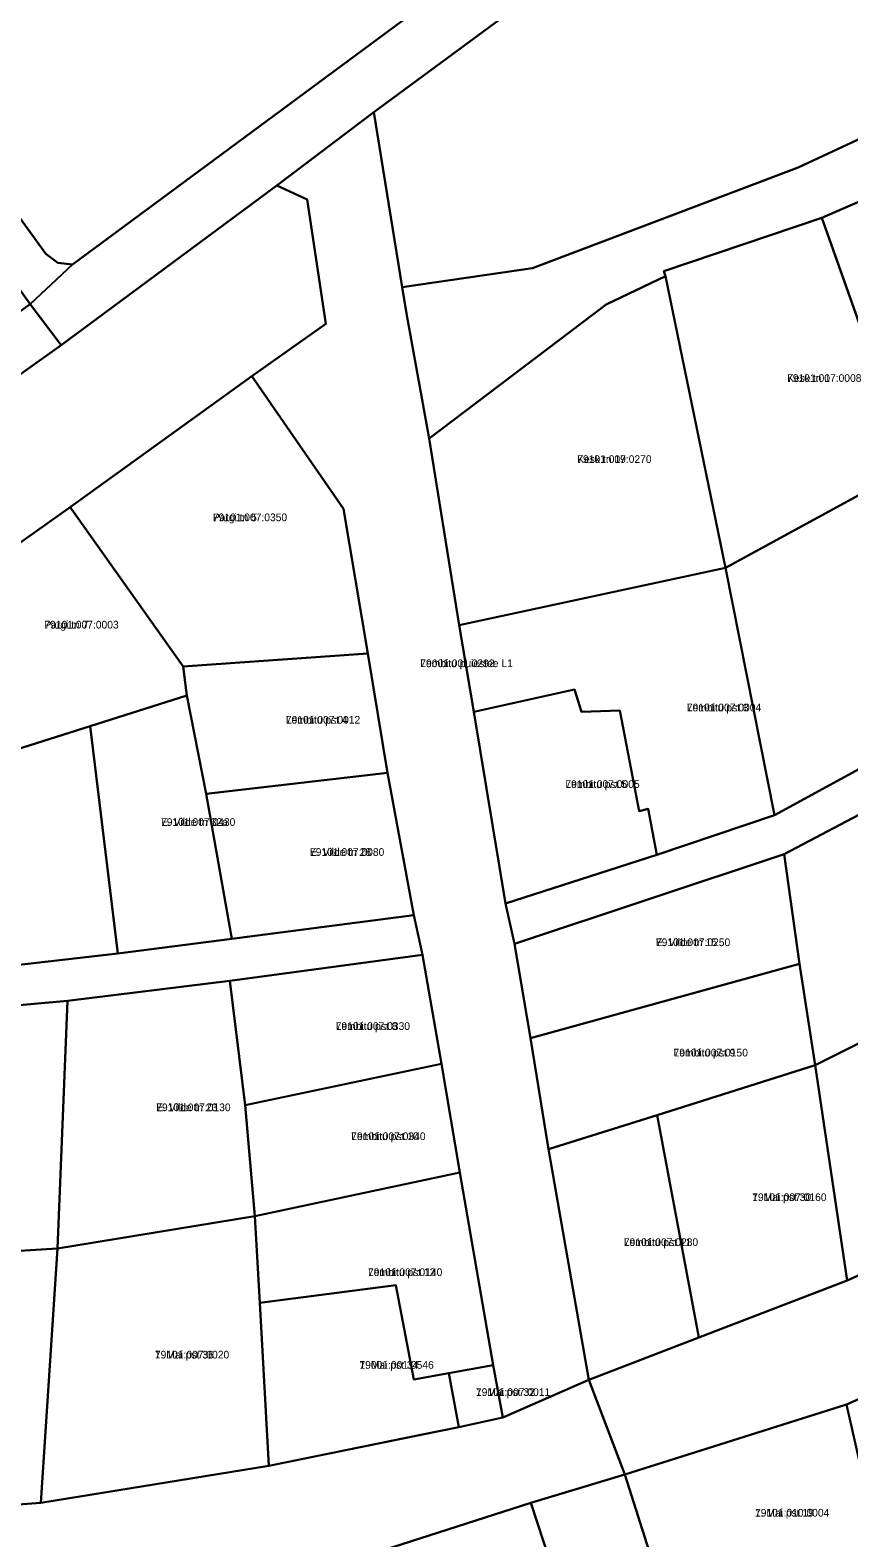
# Model space of a CAD drawing. Extents: x 587616 to 632239, y 6547421 to 6574977.
# Drawn here: x 611446.6 to 611606.3, y 6570695.1 to 6570989.5 of the extents above; entities that cross this region are included whole.
import ezdxf

# ---------------------------------------------------------------- set-up
doc = ezdxf.new("R2010")
doc.units = 0
for name, color, linetype in [('L_AADRESS', 7, 'Continuous'), ('PIIR', 7, 'Continuous'), ('TUNNUS', 7, 'Continuous')]:
    doc.layers.add(name, color=color, linetype=linetype)

msp = doc.modelspace()

# ---------------------------------------------------------------- linework, layer by layer
at = {"layer": 'PIIR'}
for points in [[(611446.63, 6570935.99), (611454.85, 6570943.73), (611564.19, 6571024.58), (611574.16, 6571034.86), (611617.76, 6571067.56), (611639.31, 6571081.15), (611661.96, 6571097.69), (611699.21, 6571124.46), (611732.93, 6571149.12), (611742.94, 6571156.35), (611778.1, 6571182.02), (611797.02, 6571195.84), (611810.31, 6571205.47), (611838.63, 6571226.7), (611846.22, 6571216.07), (611796.12, 6571181.57), (611778.84, 6571168.84), (611746.37, 6571145.45), (611736.9, 6571139.34), (611649.26, 6571075.47), (611632.53, 6571061.07), (611513.67, 6570973.46), (611494.74, 6570959.13), (611452.66, 6570927.93)], [(611556.99, 6571124.68), (611590.3, 6571148.55), (611614.86, 6571115.38), (611639.31, 6571081.15), (611617.76, 6571067.56), (611574.16, 6571034.86), (611564.19, 6571024.58), (611454.85, 6570943.73), (611452.04, 6570944.05), (611449.7, 6570945.77), (611402.13, 6571011.47), (611505.14, 6571086.78)], [(611513.67, 6570973.46), (611632.53, 6571061.07), (611674.1, 6571008.09), (611673.76, 6570998.68), (611596.46, 6570962.66), (611544.61, 6570943), (611519.18, 6570939.27)], [(611395.22, 6571006.93), (611402.13, 6571011.47), (611449.7, 6570945.77), (611452.04, 6570944.05), (611454.85, 6570943.73), (611446.63, 6570935.99), (611421.24, 6570971.29)], [(611410.78, 6570910.3), (611384.57, 6570945.39), (611421.24, 6570971.29), (611446.63, 6570935.99)], [(611494.74, 6570959.13), (611513.67, 6570973.46), (611519.18, 6570939.27), (611520.03, 6570934.12), (611524.45, 6570909.75), (611530.31, 6570873.31), (611533.19, 6570856.36), (611539.35, 6570818.99), (611541.09, 6570811.09), (611544.22, 6570792.69), (611547.78, 6570771.01), (611555.59, 6570725.99), (611538.86, 6570718.6), (611536.96, 6570728.82), (611530.42, 6570766.47), (611526.84, 6570787.65), (611523.18, 6570808.97), (611521.46, 6570816.68), (611516.34, 6570844.49), (611512.5, 6570867.77), (611507.74, 6570895.99), (611489.87, 6570921.94), (611504.31, 6570932.12), (611500.63, 6570956.37)], [(611601.1, 6570952.82), (611631.58, 6570966.1), (611641.11, 6570947.96), (611653.44, 6570923.58), (611635.81, 6570913.65), (611618.34, 6570904.12)], [(611360.46, 6570829.79), (611355.11, 6570858.39), (611452.66, 6570927.93), (611494.74, 6570959.13), (611500.63, 6570956.37), (611504.31, 6570932.12), (611489.87, 6570921.94), (611454.42, 6570896.33), (611425.42, 6570875.77), (611392.67, 6570852.6), (611388.01, 6570849.3)], [(611601.1, 6570952.82), (611618.34, 6570904.12), (611582.27, 6570884.51), (611570.61, 6570941.4), (611570.28, 6570942.38)], [(611582.27, 6570884.51), (611530.31, 6570873.31), (611524.45, 6570909.75), (611558.99, 6570935.93), (611570.61, 6570941.4)], [(611410.78, 6570910.3), (611446.63, 6570935.99), (611452.66, 6570927.93), (611355.11, 6570858.39), (611322.85, 6570834.25), (611277.47, 6570800.56), (611243.83, 6570775.62), (611206.86, 6570748.58), (611193.85, 6570758.95), (611222.49, 6570780.17), (611251.52, 6570801.55), (611290.35, 6570830.17), (611309.54, 6570844.16), (611328.74, 6570858.49), (611338.4, 6570865.67), (611345.77, 6570863.86), (611378.34, 6570887.06)], [(611454.42, 6570896.33), (611489.87, 6570921.94), (611507.74, 6570895.99), (611512.5, 6570867.77), (611476.44, 6570865.26)], [(611539.35, 6570818.99), (611568.9, 6570828.44), (611591.84, 6570836.24), (611633.59, 6570859), (611654.18, 6570870.99), (611674.66, 6570882.94), (611682.4, 6570888.06), (611679.38, 6570892.95), (611715.47, 6570915.51), (611718.31, 6570909.5), (611666.32, 6570868.57), (611657.08, 6570862.9), (611636.21, 6570850.99), (611593.71, 6570828.61), (611541.09, 6570811.09)], [(611582.27, 6570884.51), (611618.34, 6570904.12), (611633.59, 6570859), (611591.84, 6570836.24)], [(611454.42, 6570896.33), (611476.44, 6570865.26), (611477.17, 6570859.56), (611458.32, 6570853.56), (611443.72, 6570848.96), (611425.42, 6570875.77)], [(611530.31, 6570873.31), (611582.27, 6570884.51), (611591.84, 6570836.24), (611568.9, 6570828.44), (611567.19, 6570837.48), (611565.41, 6570836.99), (611561.65, 6570856.62), (611554.17, 6570856.39), (611552.85, 6570860.73), (611533.19, 6570856.36)], [(611413.65, 6570804.38), (611411.88, 6570815.74), (611401.9, 6570830.04), (611392.36, 6570843.26), (611397.04, 6570846.62), (611392.67, 6570852.6), (611425.42, 6570875.77), (611443.72, 6570848.96), (611458.32, 6570853.56), (611463.72, 6570809.2), (611421.69, 6570804.42)], [(611476.44, 6570865.26), (611512.5, 6570867.77), (611516.34, 6570844.49), (611480.97, 6570840.39), (611477.17, 6570859.56)], [(611458.32, 6570853.56), (611477.17, 6570859.56), (611480.97, 6570840.39), (611485.96, 6570812.06), (611463.72, 6570809.2)], [(611533.19, 6570856.36), (611552.85, 6570860.73), (611554.17, 6570856.39), (611561.65, 6570856.62), (611565.41, 6570836.99), (611567.19, 6570837.48), (611568.9, 6570828.44), (611539.35, 6570818.99)], [(611322.85, 6570834.25), (611355.11, 6570858.39), (611360.46, 6570829.79), (611376.44, 6570808.33), (611377.88, 6570806.42), (611391, 6570803.96), (611413.65, 6570804.38), (611421.69, 6570804.42), (611463.72, 6570809.2), (611485.96, 6570812.06), (611521.46, 6570816.68), (611523.18, 6570808.97), (611485.59, 6570803.86), (611453.91, 6570799.95), (611419.86, 6570796.94), (611384.28, 6570796.03), (611358.69, 6570800.05), (611339.59, 6570811.31)], [(611599.76, 6570787.43), (611596.74, 6570807.2), (611593.71, 6570828.61), (611636.21, 6570850.99), (611645.36, 6570810.78), (611622.77, 6570798.9)], [(611480.97, 6570840.39), (611516.34, 6570844.49), (611521.46, 6570816.68), (611485.96, 6570812.06)], [(611541.09, 6570811.09), (611593.71, 6570828.61), (611596.74, 6570807.2), (611544.22, 6570792.69)], [(611485.59, 6570803.86), (611523.18, 6570808.97), (611526.84, 6570787.65), (611488.58, 6570779.62)], [(611568.96, 6570777.63), (611547.78, 6570771.01), (611544.22, 6570792.69), (611596.74, 6570807.2), (611599.76, 6570787.43)], [(611453.91, 6570799.95), (611485.59, 6570803.86), (611488.58, 6570779.62), (611490.47, 6570757.93), (611451.97, 6570751.62)], [(611410.44, 6570752.71), (611419.86, 6570796.94), (611453.91, 6570799.95), (611451.97, 6570751.62), (611411.66, 6570749.17)], [(611599.76, 6570787.43), (611622.77, 6570798.9), (611630.69, 6570756.53), (611606.04, 6570745.37)], [(611488.58, 6570779.62), (611526.84, 6570787.65), (611530.42, 6570766.47), (611490.47, 6570757.93)], [(611568.96, 6570777.63), (611599.76, 6570787.43), (611606.04, 6570745.37), (611577.11, 6570734.25)], [(611547.78, 6570771.01), (611568.96, 6570777.63), (611577.11, 6570734.25), (611555.59, 6570725.99)], [(611490.47, 6570757.93), (611530.42, 6570766.47), (611536.96, 6570728.82), (611528.33, 6570727.26), (611521.46, 6570726.03), (611517.99, 6570744.44), (611491.43, 6570741)], [(611490.47, 6570757.93), (611491.43, 6570741), (611493.19, 6570709.17), (611448.71, 6570701.95), (611451.97, 6570751.62)], [(611427.61, 6570733.72), (611409.98, 6570732.9), (611411.66, 6570749.17), (611451.97, 6570751.62), (611448.71, 6570701.95), (611424.73, 6570700.25)], [(611491.43, 6570741), (611517.99, 6570744.44), (611521.46, 6570726.03), (611528.33, 6570727.26), (611530.28, 6570716.77), (611523.13, 6570715.3), (611493.19, 6570709.17)], [(611528.33, 6570727.26), (611536.96, 6570728.82), (611538.86, 6570718.6), (611530.28, 6570716.77)], [(611605.89, 6570721.19), (611613.19, 6570724.38), (611632.69, 6570666.47), (611617.08, 6570659.88), (611609.87, 6570658.95), (611584.9, 6570655.82), (611581.42, 6570680.18), (611612.97, 6570689.86)], [(611572.2, 6570677.38), (611562.63, 6570707.5), (611605.89, 6570721.19), (611612.97, 6570689.86), (611581.42, 6570680.18)], [(611544.29, 6570701.99), (611562.63, 6570707.5), (611572.2, 6570677.38), (611578.97, 6570654.99), (611606.7, 6570564.94), (611611.62, 6570552.25), (611618.78, 6570522.96), (611628.1, 6570462.59), (611630.58, 6570444.17), (611631.63, 6570436.86), (611611, 6570436.73), (611611.27, 6570440.74), (611608.87, 6570462.33), (611605.98, 6570482.32), (611599.38, 6570522), (611588.44, 6570559.17), (611562.57, 6570643.33), (611561.17, 6570648.58), (611557.87, 6570660.58), (611554.36, 6570671.22)], [(611528.58, 6570662.68), (611518.41, 6570660.08), (611515.53, 6570692.73), (611544.29, 6570701.99), (611554.36, 6570671.22), (611528.44, 6570664.01)]]:
    msp.add_lwpolyline(points, close=True, dxfattribs=at)
for points in [[(611694, 6570998.65), (611656.11, 6570977.68), (611631.58, 6570966.1), (611601.1, 6570952.82), (611570.28, 6570942.38), (611570.61, 6570941.4), (611558.99, 6570935.93), (611524.45, 6570909.75), (611520.03, 6570934.12), (611519.18, 6570939.27), (611544.61, 6570943), (611596.46, 6570962.66), (611673.74, 6570998.74)], [(611144.06, 6570824.65), (611173.18, 6570786.28), (611193.85, 6570758.95), (611206.86, 6570748.58), (611224.54, 6570733.13), (611247.98, 6570722.86), (611274.66, 6570715.97), (611296.76, 6570710.01), (611311.91, 6570708.9), (611330.07, 6570703.81), (611350.28, 6570700.48), (611402.18, 6570698.3), (611424.73, 6570700.25), (611448.71, 6570701.95), (611493.19, 6570709.17), (611530.28, 6570716.77), (611538.86, 6570718.6), (611555.59, 6570725.99), (611562.63, 6570707.5), (611544.29, 6570701.99), (611515.53, 6570692.73)], [(611613.19, 6570724.38), (611605.89, 6570721.19), (611562.63, 6570707.5), (611555.59, 6570725.99), (611577.11, 6570734.25), (611606.04, 6570745.37), (611630.69, 6570756.53)]]:
    msp.add_lwpolyline(points, dxfattribs=at)

# ---------------------------------------------------------------- texts
at = {"layer": 'L_AADRESS'}
for s, p in [('Kesk tn 17', (611594.31, 6570920.79)), ('Kesk tn 19', (611553.36, 6570904.97)), ('Pargi tn 5', (611482.25, 6570893.6)), ('Pargi tn 7', (611449.38, 6570872.65)), ('Lembitu puiestee L1', (611522.73, 6570865.11)), ('Lembitu pst 3', (611574.75, 6570856.48)), ('Lembitu pst 4', (611496.51, 6570854.08)), ('Lembitu pst 5', (611551.04, 6570841.53)), ('E. Vilde tn 32a', (611472.14, 6570834.12)), ('E. Vilde tn 28', (611501.21, 6570828.27)), ('E. Vilde tn 15', (611568.71, 6570810.65)), ('Lembitu pst 8', (611506.23, 6570794.29)), ('Lembitu pst 9', (611572.16, 6570789.11)), ('E. Vilde tn 23', (611471.22, 6570778.43)), ('Lembitu pst 10', (611509.26, 6570772.79)), ('1. Mai pst 30', (611587.5, 6570760.89)), ('Lembitu pst 11', (611562.45, 6570752.11)), ('Lembitu pst 12', (611512.53, 6570746.25)), ('1. Mai pst 36', (611470.95, 6570730.15)), ('1. Mai pst 34', (611510.86, 6570728.15)), ('1. Mai pst 32', (611533.59, 6570722.84)), ('1. Mai pst 19', (611588.04, 6570699.29))]:
    msp.add_text(s, height=1.5, dxfattribs=at).set_placement(p)
at = {"layer": 'TUNNUS'}
for s, p in [('79101:007:0008', (611594.31, 6570920.79)), ('79101:007:0270', (611553.36, 6570904.97)), ('79101:007:0350', (611482.25, 6570893.6)), ('79101:007:0003', (611449.38, 6570872.65)), ('79001:001:0292', (611522.73, 6570865.11)), ('79101:007:0004', (611574.75, 6570856.48)), ('79101:007:0012', (611496.51, 6570854.08)), ('79101:007:0005', (611551.04, 6570841.53)), ('79101:007:0430', (611472.14, 6570834.12)), ('79101:007:0080', (611501.21, 6570828.27)), ('79101:007:0250', (611568.71, 6570810.65)), ('79101:007:0330', (611506.23, 6570794.29)), ('79101:007:0150', (611572.16, 6570789.11)), ('79101:007:0130', (611471.22, 6570778.43)), ('79101:007:0340', (611509.26, 6570772.79)), ('79101:007:0160', (611587.5, 6570760.89)), ('79101:007:0280', (611562.45, 6570752.11)), ('79101:007:0140', (611512.53, 6570746.25)), ('79101:007:0020', (611470.95, 6570730.15)), ('79001:001:0546', (611510.86, 6570728.15)), ('79101:007:0011', (611533.59, 6570722.84)), ('79101:010:0004', (611588.04, 6570699.29))]:
    msp.add_text(s, height=1.5, dxfattribs=at).set_placement(p)

doc.saveas('drawing.dxf')
